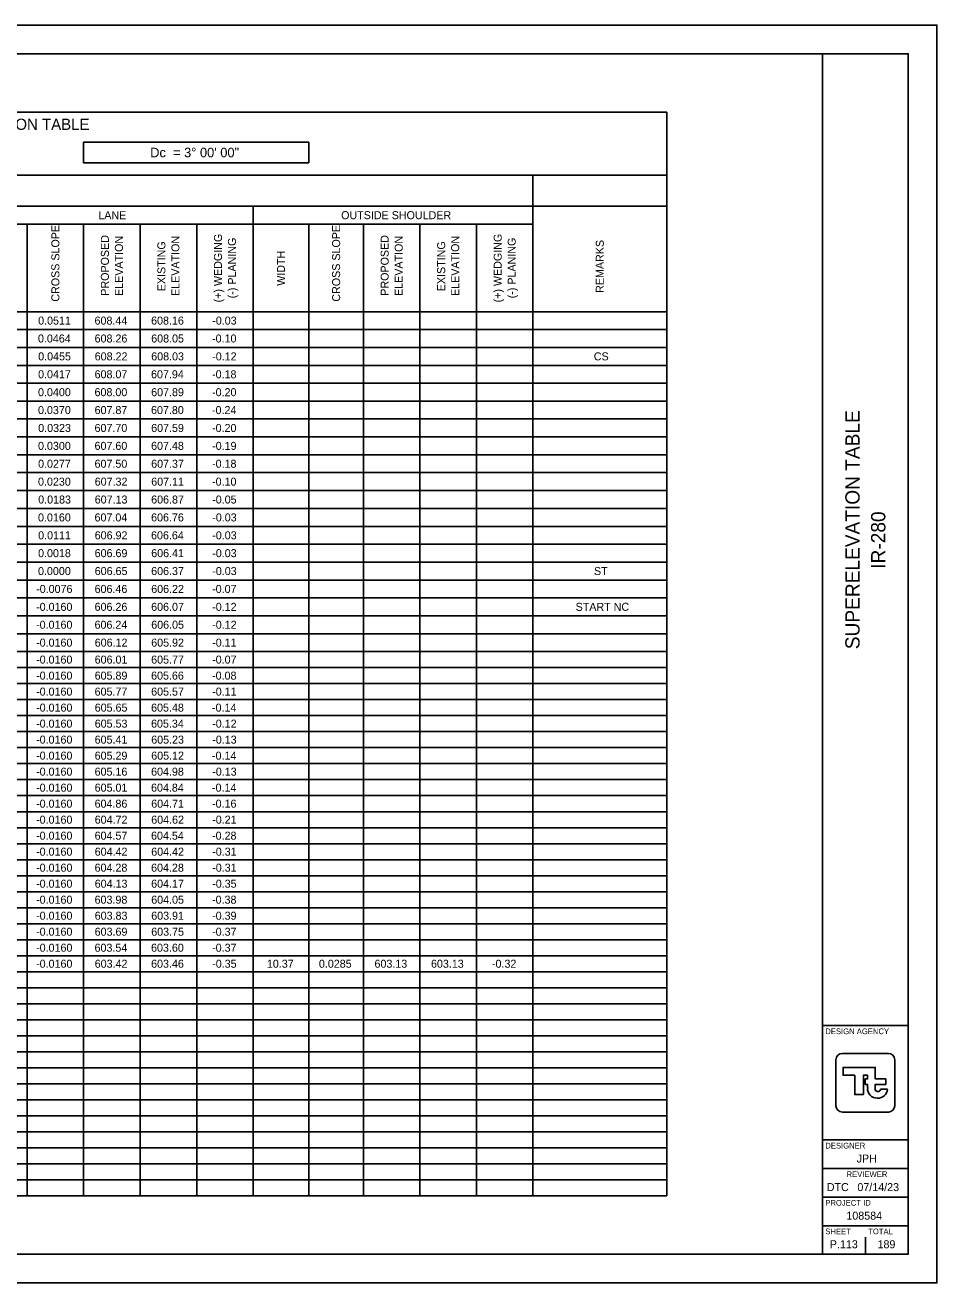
# Model space of a CAD drawing. Extents: x 0 to 34, y 0 to 22.
# Drawn here: x 18.06 to 34, y 0 to 22 of the extents above; entities that cross this region are included whole.
import ezdxf

# ---------------------------------------------------------------- set-up
doc = ezdxf.new("R2010")
doc.units = 0
for name, color, linetype in [('Default', 7, 'Continuous'), ('SH_Border', 7, 'Continuous'), ('SH_Cut_Line', 7, 'Continuous'), ('SH_Data', 7, 'Continuous')]:
    doc.layers.add(name, color=color, linetype=linetype)

msp = doc.modelspace()

# ---------------------------------------------------------------- linework, layer by layer
at = {"layer": 'Default'}
for p, q in [((4.225, 20.48), (29.277, 20.48)), ((29.277, 20.48), (29.277, 1.522)), ((19.081, 19.953), (23.018, 19.953)), ((19.081, 19.953), (19.081, 19.591)), ((23.018, 19.953), (23.018, 19.591)), ((19.081, 19.591), (23.018, 19.591)), ((4.225, 19.376), (29.277, 19.376)), ((26.938, 19.376), (26.938, 1.522)), ((4.225, 18.833), (29.277, 18.833)), ((22.046, 18.833), (22.046, 1.522)), ((6.3, 18.52), (26.938, 18.52)), ((18.093, 18.52), (18.093, 1.522)), ((19.081, 18.52), (19.081, 1.522)), ((20.07, 18.52), (20.07, 1.522)), ((21.058, 18.52), (21.058, 1.522)), ((23.018, 18.52), (23.018, 1.522)), ((23.973, 18.52), (23.973, 1.522)), ((24.961, 18.52), (24.961, 1.522)), ((25.95, 18.52), (25.95, 1.522)), ((4.225, 16.988), (29.277, 16.988)), ((4.225, 16.675), (29.277, 16.675)), ((4.225, 16.362), (29.277, 16.362)), ((4.225, 16.049), (29.277, 16.049)), ((4.225, 15.736), (29.277, 15.736)), ((4.225, 15.424), (29.277, 15.424)), ((4.225, 15.111), (29.277, 15.111)), ((4.225, 14.798), (29.277, 14.798)), ((4.225, 14.485), (29.277, 14.485)), ((4.225, 14.172), (29.277, 14.172)), ((4.225, 13.859), (29.277, 13.859)), ((4.225, 13.546), (29.277, 13.546)), ((4.225, 13.233), (29.277, 13.233)), ((4.225, 12.92), (29.277, 12.92)), ((4.225, 12.607), (29.277, 12.607)), ((4.225, 12.294), (29.277, 12.294)), ((4.225, 11.981), (29.277, 11.981)), ((4.225, 11.668), (29.277, 11.668)), ((4.225, 11.355), (29.277, 11.355)), ((4.225, 11.042), (29.277, 11.042)), ((4.225, 10.762), (29.277, 10.762)), ((4.225, 10.482), (29.277, 10.482)), ((4.225, 10.202), (29.277, 10.202)), ((4.225, 9.922), (29.277, 9.922)), ((4.225, 9.642), (29.277, 9.642)), ((4.225, 9.362), (29.277, 9.362)), ((4.225, 9.082), (29.277, 9.082)), ((4.225, 8.802), (29.277, 8.802)), ((4.225, 8.522), (29.277, 8.522)), ((4.225, 8.242), (29.277, 8.242)), ((4.225, 7.962), (29.277, 7.962)), ((4.225, 7.682), (29.277, 7.682)), ((4.225, 7.402), (29.277, 7.402)), ((4.225, 7.122), (29.277, 7.122)), ((4.225, 6.842), (29.277, 6.842)), ((4.225, 6.562), (29.277, 6.562)), ((4.225, 6.282), (29.277, 6.282)), ((4.225, 6.002), (29.277, 6.002)), ((4.225, 5.722), (29.277, 5.722)), ((4.225, 5.442), (29.277, 5.442)), ((4.225, 5.162), (29.277, 5.162)), ((4.225, 4.882), (29.277, 4.882)), ((4.225, 4.602), (29.277, 4.602)), ((4.225, 4.322), (29.277, 4.322)), ((4.225, 4.042), (29.277, 4.042)), ((4.225, 3.762), (29.277, 3.762)), ((4.225, 3.482), (29.277, 3.482)), ((4.225, 3.202), (29.277, 3.202)), ((4.225, 2.922), (29.277, 2.922)), ((4.225, 2.642), (29.277, 2.642)), ((4.225, 2.362), (29.277, 2.362)), ((4.225, 2.082), (29.277, 2.082)), ((4.225, 1.802), (29.277, 1.802)), ((4.225, 1.522), (29.277, 1.522))]:
    msp.add_line(p, q, dxfattribs=at)
at = {"layer": 'SH_Border'}
for p, q in [((32, 0.5), (32, 21.5)), ((32, 4.5), (33.5, 4.5)), ((32, 2.5), (33.5, 2.5)), ((32, 2), (33.5, 2)), ((32, 1.5), (33.5, 1.5)), ((32, 1), (33.5, 1))]:
    msp.add_line(p, q, dxfattribs=at)
msp.add_lwpolyline([(1.5, 21.5), (33.5, 21.5), (33.5, 0.5), (1.5, 0.5)], close=True, dxfattribs=at)
at = {"layer": 'SH_Cut_Line'}
msp.add_lwpolyline([(0, 0), (34, 0), (34, 22), (0, 22)], close=True, dxfattribs=at)
at = {"layer": 'SH_Data'}
for p, q in [((32.75, 3.5), (32.75, 3.5)), ((32.791, 3.415), (32.791, 3.415)), ((33.136, 3.385), (33.015, 3.385)), ((32.375, 0.675), (32.375, 0.675)), ((32.75, 0.5), (32.75, 0.8))]:
    msp.add_line(p, q, dxfattribs=at)
for points in [[(32.348, 4.014), (33.152, 4.014)], [(32.236, 3.099), (32.236, 3.901)], [(32.922, 3.399), (32.922, 3.47), (33.107, 3.47), (33.107, 3.568), (32.922, 3.568), (32.922, 3.768), (32.361, 3.768), (32.361, 3.632), (32.566, 3.632), (32.566, 3.294), (32.715, 3.294), (32.715, 3.63), (32.79, 3.63), (32.79, 3.568), (32.748, 3.568), (32.748, 3.47), (32.79, 3.47), (32.79, 3.415), (32.791, 3.415)], [(33.264, 3.901), (33.264, 3.099)], [(33.152, 2.986), (32.348, 2.986)]]:
    msp.add_lwpolyline(points, dxfattribs=at)
for centre, radius, start, end in [((32.348, 3.901), 0.113, 90, 180), ((33.152, 3.901), 0.113, 360, 90), ((32.949, 3.392), 0.16, 171.8856, 274.8323), ((32.968, 3.392), 0.0473, 171.8856, 350.9243), ((32.976, 3.392), 0.16, 265.1677, 357.3201), ((32.348, 3.099), 0.113, 180, 270), ((33.152, 3.099), 0.113, 270, 360)]:
    msp.add_arc(centre, radius, start, end, dxfattribs=at)

# ---------------------------------------------------------------- texts
at = {"layer": 'Default'}
for s, height, p in [('WOO/LUC-280-06.20/00.00 - SUPERELEVATION TABLE', 0.196, (12.425, 20.168)), ('Dc  = 3° 00\' 00"', 0.168, (20.245, 19.688)), ('LANE', 0.14, (19.338, 18.606)), ('OUTSIDE SHOULDER', 0.14, (23.584, 18.606)), ('0.0511', 0.14, (18.286, 16.762)), ('608.44', 0.14, (19.272, 16.762)), ('608.16', 0.14, (20.261, 16.762)), ('-0.03', 0.14, (21.33, 16.762)), ('0.0464', 0.14, (18.283, 16.449)), ('608.26', 0.14, (19.273, 16.449)), ('608.05', 0.14, (20.263, 16.449)), ('-0.10', 0.14, (21.327, 16.449)), ('0.0455', 0.14, (18.287, 16.136)), ('608.22', 0.14, (19.275, 16.136)), ('608.03', 0.14, (20.263, 16.136)), ('-0.12', 0.14, (21.329, 16.136)), ('CS', 0.14, (28.002, 16.136)), ('0.0417', 0.14, (18.285, 15.823)), ('608.07', 0.14, (19.273, 15.823)), ('607.94', 0.14, (20.26, 15.823)), ('-0.18', 0.14, (21.327, 15.823)), ('0.0400', 0.14, (18.284, 15.51)), ('608.00', 0.14, (19.272, 15.51)), ('607.89', 0.14, (20.262, 15.51)), ('-0.20', 0.14, (21.327, 15.51)), ('0.0370', 0.14, (18.284, 15.197)), ('607.87', 0.14, (19.273, 15.197)), ('607.80', 0.14, (20.26, 15.197)), ('-0.24', 0.14, (21.326, 15.197)), ('0.0323', 0.14, (18.287, 14.884)), ('607.70', 0.14, (19.272, 14.884)), ('607.59', 0.14, (20.262, 14.884)), ('-0.20', 0.14, (21.327, 14.884)), ('0.0300', 0.14, (18.284, 14.571)), ('607.60', 0.14, (19.272, 14.571)), ('607.48', 0.14, (20.261, 14.571)), ('-0.19', 0.14, (21.328, 14.571)), ('0.0277', 0.14, (18.285, 14.258)), ('607.50', 0.14, (19.272, 14.258)), ('607.37', 0.14, (20.262, 14.258)), ('-0.18', 0.14, (21.327, 14.258)), ('0.0230', 0.14, (18.284, 13.945)), ('607.32', 0.14, (19.275, 13.945)), ('607.11', 0.14, (20.263, 13.945)), ('-0.10', 0.14, (21.327, 13.945)), ('0.0183', 0.14, (18.287, 13.632)), ('607.13', 0.14, (19.275, 13.632)), ('606.87', 0.14, (20.262, 13.632)), ('-0.05', 0.14, (21.329, 13.632)), ('0.0160', 0.14, (18.284, 13.319)), ('607.04', 0.14, (19.272, 13.319)), ('606.76', 0.14, (20.261, 13.319)), ('-0.03', 0.14, (21.33, 13.319)), ('0.0111', 0.14, (18.286, 13.006)), ('606.92', 0.14, (19.275, 13.006)), ('606.64', 0.14, (20.26, 13.006)), ('-0.03', 0.14, (21.33, 13.006)), ('0.0018', 0.14, (18.285, 12.694)), ('606.69', 0.14, (19.274, 12.694)), ('606.41', 0.14, (20.263, 12.694)), ('-0.03', 0.14, (21.33, 12.694)), ('0.0000', 0.14, (18.284, 12.381)), ('606.65', 0.14, (19.275, 12.381)), ('606.37', 0.14, (20.262, 12.381)), ('-0.03', 0.14, (21.33, 12.381)), ('ST', 0.14, (28.005, 12.381)), ('-0.0076', 0.14, (18.251, 12.068)), ('606.46', 0.14, (19.273, 12.068)), ('606.22', 0.14, (20.263, 12.068)), ('-0.07', 0.14, (21.328, 12.068)), ('-0.0160', 0.14, (18.25, 11.755)), ('606.26', 0.14, (19.273, 11.755)), ('606.07', 0.14, (20.262, 11.755)), ('-0.12', 0.14, (21.329, 11.755)), ('START NC', 0.14, (27.684, 11.755)), ('-0.0160', 0.14, (18.25, 11.442)), ('606.24', 0.14, (19.272, 11.442)), ('606.05', 0.14, (20.263, 11.442)), ('-0.12', 0.14, (21.329, 11.442)), ('-0.0160', 0.14, (18.25, 11.129)), ('606.12', 0.14, (19.275, 11.129)), ('605.92', 0.14, (20.263, 11.129)), ('-0.11', 0.14, (21.329, 11.129)), ('-0.0160', 0.14, (18.25, 10.832)), ('606.01', 0.14, (19.274, 10.832)), ('605.77', 0.14, (20.262, 10.832)), ('-0.07', 0.14, (21.328, 10.832)), ('-0.0160', 0.14, (18.25, 10.552)), ('605.89', 0.14, (19.274, 10.552)), ('605.66', 0.14, (20.261, 10.552)), ('-0.08', 0.14, (21.327, 10.552)), ('-0.0160', 0.14, (18.25, 10.272)), ('605.77', 0.14, (19.273, 10.272)), ('605.57', 0.14, (20.262, 10.272)), ('-0.11', 0.14, (21.329, 10.272)), ('-0.0160', 0.14, (18.25, 9.992)), ('605.65', 0.14, (19.275, 9.992)), ('605.48', 0.14, (20.261, 9.992)), ('-0.14', 0.14, (21.326, 9.992)), ('-0.0160', 0.14, (18.25, 9.712)), ('605.53', 0.14, (19.275, 9.712)), ('605.34', 0.14, (20.26, 9.712)), ('-0.12', 0.14, (21.329, 9.712)), ('-0.0160', 0.14, (18.25, 9.432)), ('605.41', 0.14, (19.274, 9.432)), ('605.23', 0.14, (20.263, 9.432)), ('-0.13', 0.14, (21.33, 9.432)), ('-0.0160', 0.14, (18.25, 9.152)), ('605.29', 0.14, (19.274, 9.152)), ('605.12', 0.14, (20.263, 9.152)), ('-0.14', 0.14, (21.326, 9.152)), ('-0.0160', 0.14, (18.25, 8.872)), ('605.16', 0.14, (19.273, 8.872)), ('604.98', 0.14, (20.261, 8.872)), ('-0.13', 0.14, (21.33, 8.872)), ('-0.0160', 0.14, (18.25, 8.592)), ('605.01', 0.14, (19.274, 8.592)), ('604.84', 0.14, (20.26, 8.592)), ('-0.14', 0.14, (21.326, 8.592)), ('-0.0160', 0.14, (18.25, 8.312)), ('604.86', 0.14, (19.273, 8.312)), ('604.71', 0.14, (20.263, 8.312)), ('-0.16', 0.14, (21.327, 8.312)), ('-0.0160', 0.14, (18.25, 8.032)), ('604.72', 0.14, (19.275, 8.032)), ('604.62', 0.14, (20.263, 8.032)), ('-0.21', 0.14, (21.329, 8.032)), ('-0.0160', 0.14, (18.25, 7.752)), ('604.57', 0.14, (19.273, 7.752)), ('604.54', 0.14, (20.26, 7.752)), ('-0.28', 0.14, (21.327, 7.752)), ('-0.0160', 0.14, (18.25, 7.472)), ('604.42', 0.14, (19.275, 7.472)), ('604.42', 0.14, (20.263, 7.472)), ('-0.31', 0.14, (21.329, 7.472)), ('-0.0160', 0.14, (18.25, 7.192)), ('604.28', 0.14, (19.273, 7.192)), ('604.28', 0.14, (20.261, 7.192)), ('-0.31', 0.14, (21.329, 7.192)), ('-0.0160', 0.14, (18.25, 6.912)), ('604.13', 0.14, (19.275, 6.912)), ('604.17', 0.14, (20.262, 6.912)), ('-0.35', 0.14, (21.329, 6.912)), ('-0.0160', 0.14, (18.25, 6.632)), ('603.98', 0.14, (19.273, 6.632)), ('604.05', 0.14, (20.263, 6.632)), ('-0.38', 0.14, (21.327, 6.632)), ('-0.0160', 0.14, (18.25, 6.352)), ('603.83', 0.14, (19.275, 6.352)), ('603.91', 0.14, (20.263, 6.352)), ('-0.39', 0.14, (21.328, 6.352)), ('-0.0160', 0.14, (18.25, 6.072)), ('603.69', 0.14, (19.274, 6.072)), ('603.75', 0.14, (20.263, 6.072)), ('-0.37', 0.14, (21.328, 6.072)), ('-0.0160', 0.14, (18.25, 5.792)), ('603.54', 0.14, (19.272, 5.792)), ('603.60', 0.14, (20.26, 5.792)), ('-0.37', 0.14, (21.328, 5.792)), ('-0.0160', 0.14, (18.25, 5.512)), ('603.42', 0.14, (19.275, 5.512)), ('603.46', 0.14, (20.261, 5.512)), ('-0.35', 0.14, (21.329, 5.512)), ('10.37', 0.14, (22.286, 5.512)), ('0.0285', 0.14, (23.195, 5.512)), ('603.13', 0.14, (24.167, 5.512)), ('603.13', 0.14, (25.155, 5.512)), ('-0.32', 0.14, (26.221, 5.512))]:
    msp.add_text(s, height=height, dxfattribs=at).set_placement(p)
for s, p in [('CROSS SLOPE', (18.657, 17.163)), ('CROSS SLOPE', (23.566, 17.163)), ('PROPOSED ', (19.523, 17.267)), ('ELEVATION', (19.768, 17.263)), ('ELEVATION', (20.756, 17.263)), ('(+) WEDGING', (21.5, 17.15)), ('(-) PLANING', (21.745, 17.222)), ('PROPOSED ', (24.415, 17.267)), ('ELEVATION', (24.66, 17.263)), ('ELEVATION', (25.648, 17.263)), ('(+) WEDGING', (26.391, 17.15)), ('(-) PLANING', (26.636, 17.222)), ('EXISTING ', (20.511, 17.345)), ('EXISTING ', (25.403, 17.345)), ('REMARKS', (28.177, 17.317)), ('WIDTH', (22.602, 17.441))]:
    msp.add_text(s, height=0.14, rotation=90, dxfattribs=at).set_placement(p)
at = {"layer": 'SH_Data'}
for s, p in [('SUPERELEVATION TABLE', (32.65, 11.084)), ('IR-280', (33.1, 12.491))]:
    msp.add_text(s, height=0.25, rotation=90, dxfattribs=at).set_placement(p)
for s, height, p in [('DESIGN AGENCY', 0.1, (32.05, 4.35)), ('DESIGNER', 0.1, (32.05, 2.35)), ('JPH', 0.14, (32.598, 2.105)), ('REVIEWER', 0.1, (32.422, 1.85)), ('DTC', 0.14, (32.076, 1.605)), ('07/14/23', 0.14, (32.611, 1.605)), ('PROJECT ID', 0.1, (32.05, 1.35)), ('108584', 0.14, (32.418, 1.105)), ('SHEET', 0.1, (32.05, 0.85)), ('TOTAL', 0.1, (32.8, 0.85)), ('P.113', 0.14, (32.129, 0.605)), ('189', 0.14, (32.963, 0.605))]:
    msp.add_text(s, height=height, dxfattribs=at).set_placement(p)

doc.saveas('drawing.dxf')
